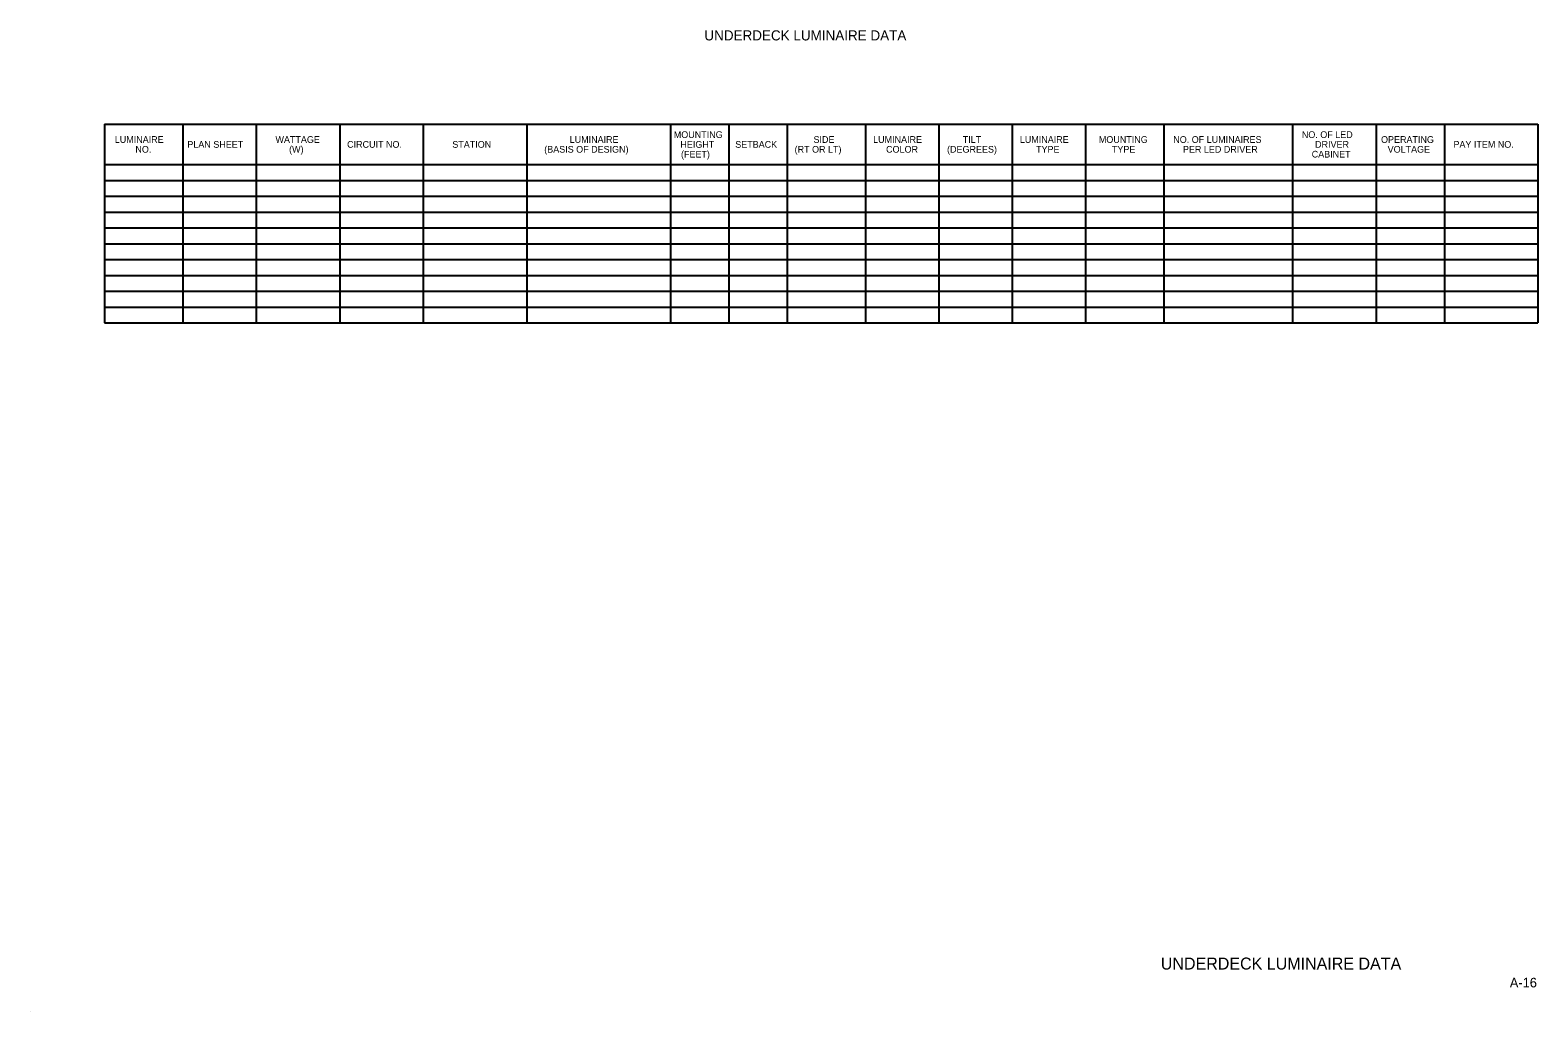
# Model space of a CAD drawing. Extents: x -830028.7 to -830013, y 1290283.4 to 1290293.6.
import ezdxf

# ---------------------------------------------------------------- set-up
doc = ezdxf.new("R2010")
doc.units = 0
for name, color, linetype in [('AdhocPoint_dp', 7, 'Continuous'), ('SumBoxBorder_dp', 7, 'Continuous'), ('SumBoxLines_dp', 7, 'Continuous'), ('SumBoxLinesMin_dp', 7, 'Continuous'), ('TextLabel', 7, 'Continuous'), ('TextMisc', 7, 'Continuous'), ('TextShtNo', 7, 'Continuous')]:
    doc.layers.add(name, color=color, linetype=linetype)

msp = doc.modelspace()

# ---------------------------------------------------------------- linework, layer by layer
at = {"layer": 'AdhocPoint_dp'}
msp.add_line((-830028.694, 1290283.415), (-830028.694, 1290283.415), dxfattribs=at)
at = {"layer": 'SumBoxBorder_dp'}
for p, q in [((-830027.917, 1290292.667), (-830012.97, 1290292.667)), ((-830027.917, 1290292.667), (-830012.97, 1290292.667)), ((-830027.917, 1290292.667), (-830027.917, 1290290.597)), ((-830012.97, 1290292.667), (-830012.97, 1290290.597)), ((-830027.917, 1290292.247), (-830012.97, 1290292.247)), ((-830027.917, 1290292.247), (-830012.97, 1290292.247)), ((-830027.917, 1290290.597), (-830012.97, 1290290.597))]:
    msp.add_line(p, q, dxfattribs=at)
at = {"layer": 'SumBoxLines_dp'}
for p, q in [((-830027.1, 1290292.667), (-830027.1, 1290290.597)), ((-830027.1, 1290292.667), (-830027.1, 1290290.597)), ((-830026.335, 1290292.667), (-830026.335, 1290290.597)), ((-830026.335, 1290292.667), (-830026.335, 1290290.597)), ((-830025.465, 1290292.667), (-830025.465, 1290290.597)), ((-830025.465, 1290292.667), (-830025.465, 1290290.597)), ((-830024.595, 1290292.667), (-830024.595, 1290290.597)), ((-830024.595, 1290292.667), (-830024.595, 1290290.597)), ((-830023.515, 1290292.667), (-830023.515, 1290290.597)), ((-830023.515, 1290292.667), (-830023.515, 1290290.597)), ((-830022.015, 1290292.667), (-830022.015, 1290290.597)), ((-830022.015, 1290292.667), (-830022.015, 1290290.597)), ((-830021.407, 1290292.667), (-830021.407, 1290290.597)), ((-830021.407, 1290292.667), (-830021.407, 1290290.597)), ((-830020.8, 1290292.667), (-830020.8, 1290290.597)), ((-830020.8, 1290292.667), (-830020.8, 1290290.597)), ((-830019.982, 1290292.667), (-830019.982, 1290290.597)), ((-830019.982, 1290292.667), (-830019.982, 1290290.597)), ((-830019.217, 1290292.667), (-830019.217, 1290290.597)), ((-830019.217, 1290292.667), (-830019.217, 1290290.597)), ((-830018.452, 1290292.667), (-830018.452, 1290290.597)), ((-830018.452, 1290292.667), (-830018.452, 1290290.597)), ((-830017.687, 1290292.667), (-830017.687, 1290290.597)), ((-830017.687, 1290292.667), (-830017.687, 1290290.597)), ((-830016.87, 1290292.667), (-830016.87, 1290290.597)), ((-830016.87, 1290292.667), (-830016.87, 1290290.597)), ((-830015.527, 1290292.667), (-830015.527, 1290290.597)), ((-830014.657, 1290292.667), (-830014.657, 1290290.597)), ((-830013.945, 1290292.667), (-830013.945, 1290290.597))]:
    msp.add_line(p, q, dxfattribs=at)
at = {"layer": 'SumBoxLinesMin_dp'}
for p, q in [((-830027.917, 1290292.082), (-830012.97, 1290292.082)), ((-830027.917, 1290292.082), (-830012.97, 1290292.082)), ((-830027.917, 1290291.917), (-830012.97, 1290291.917)), ((-830027.917, 1290291.917), (-830012.97, 1290291.917)), ((-830027.917, 1290291.752), (-830012.97, 1290291.752)), ((-830027.917, 1290291.752), (-830012.97, 1290291.752)), ((-830027.917, 1290291.587), (-830012.97, 1290291.587)), ((-830027.917, 1290291.587), (-830012.97, 1290291.587)), ((-830027.917, 1290291.422), (-830012.97, 1290291.422)), ((-830027.917, 1290291.422), (-830012.97, 1290291.422)), ((-830027.917, 1290291.257), (-830012.97, 1290291.257)), ((-830027.917, 1290291.257), (-830012.97, 1290291.257)), ((-830027.917, 1290291.092), (-830012.97, 1290291.092)), ((-830027.917, 1290291.092), (-830012.97, 1290291.092)), ((-830027.917, 1290290.927), (-830012.97, 1290290.927)), ((-830027.917, 1290290.927), (-830012.97, 1290290.927)), ((-830027.917, 1290290.762), (-830012.97, 1290290.762)), ((-830027.917, 1290290.762), (-830012.97, 1290290.762))]:
    msp.add_line(p, q, dxfattribs=at)

# ---------------------------------------------------------------- texts
at = {"layer": 'TextLabel'}
for s, height, p in [('UNDERDECK LUMINAIRE DATA', 0.105, (-830021.662, 1290293.541)), ('LUMINAIRE', 0.07, (-830027.811, 1290292.473)), ('PLAN SHEET', 0.07, (-830027.054, 1290292.422)), ('WATTAGE', 0.07, (-830026.135, 1290292.473)), ('CIRCUIT NO.', 0.07, (-830025.388, 1290292.422)), ('STATION', 0.07, (-830024.291, 1290292.422)), ('LUMINAIRE', 0.07, (-830023.067, 1290292.473)), ('MOUNTING', 0.07, (-830021.981, 1290292.524)), ('HEIGHT', 0.07, (-830021.912, 1290292.422)), ('SETBACK', 0.07, (-830021.34, 1290292.422)), ('SIDE', 0.07, (-830020.524, 1290292.473)), ('LUMINAIRE', 0.07, (-830019.902, 1290292.473)), ('TILT', 0.07, (-830018.968, 1290292.473)), ('LUMINAIRE', 0.07, (-830018.372, 1290292.473)), ('MOUNTING', 0.07, (-830017.548, 1290292.473)), ('NO. OF LUMINAIRES', 0.07, (-830016.772, 1290292.473)), ('NO. OF LED', 0.07, (-830015.431, 1290292.524)), ('OPERATING', 0.07, (-830014.605, 1290292.473)), ('PAY ITEM NO.', 0.07, (-830013.85, 1290292.422)), ('NO.', 0.07, (-830027.596, 1290292.371)), ('(W)', 0.07, (-830025.993, 1290292.371)), ('(BASIS OF DESIGN)', 0.07, (-830023.332, 1290292.371)), ('(FEET)', 0.07, (-830021.906, 1290292.32)), ('(RT OR LT)', 0.07, (-830020.721, 1290292.371)), ('COLOR', 0.07, (-830019.767, 1290292.371)), ('(DEGREES)', 0.07, (-830019.131, 1290292.371)), ('TYPE', 0.07, (-830018.203, 1290292.371)), ('TYPE', 0.07, (-830017.412, 1290292.371)), ('PER LED DRIVER', 0.07, (-830016.671, 1290292.371)), ('CABINET', 0.07, (-830015.328, 1290292.32)), ('DRIVER', 0.07, (-830015.293, 1290292.422)), ('VOLTAGE', 0.07, (-830014.536, 1290292.371))]:
    msp.add_text(s, height=height, dxfattribs=at).set_placement(p)
at = {"layer": 'TextMisc'}
msp.add_text('UNDERDECK LUMINAIRE DATA ', height=0.125, dxfattribs=at).set_placement((-830016.902, 1290283.856))
at = {"layer": 'TextShtNo'}
msp.add_text('A-16', height=0.1, dxfattribs=at).set_placement((-830013.262, 1290283.67))

doc.saveas('drawing.dxf')
